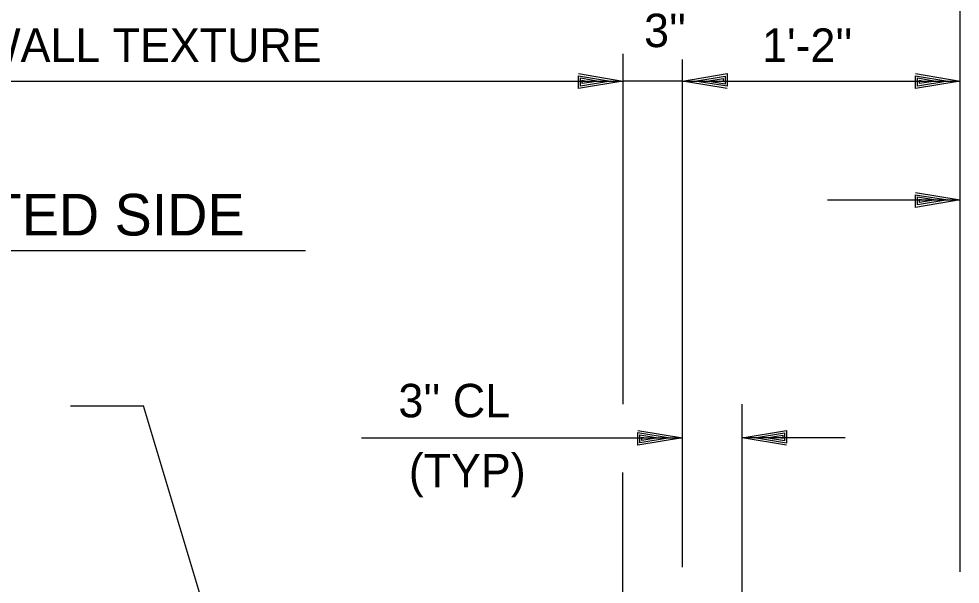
# Model space of a CAD drawing. Extents: x 22369.6 to 22428.3, y 22369.6 to 22415.
# Drawn here: x 22412.13 to 22417.4, y 22393.85 to 22397.02 of the extents above; entities that cross this region are included whole.
import ezdxf

# ---------------------------------------------------------------- set-up
doc = ezdxf.new("R2010")
doc.units = 0
for name, color, linetype in [('Level 1', 7, 'Continuous'), ('Level 10', 7, 'Continuous'), ('Level 2', 7, 'Continuous'), ('Level 4', 7, 'Continuous'), ('Level 8', 7, 'Continuous')]:
    doc.layers.add(name, color=color, linetype=linetype)

msp = doc.modelspace()

# ---------------------------------------------------------------- linework, layer by layer
at = {"layer": 'Level 1'}
for p, q in [((22417.4003, 22393.9179), (22417.4003, 22397.5025)), ((22415.5114, 22396.8216), (22415.5114, 22394.857)), ((22415.8447, 22393.9437), (22415.8447, 22396.7903)), ((22410.6541, 22396.6688), (22415.5114, 22396.6688)), ((22415.419, 22396.6688), (22415.419, 22396.6688)), ((22415.8447, 22396.6688), (22415.5114, 22396.6688)), ((22415.5114, 22396.6688), (22415.5114, 22396.6688)), ((22415.8447, 22396.6688), (22417.4003, 22396.6688)), ((22415.8447, 22396.6688), (22415.8447, 22396.6688)), ((22415.8447, 22396.6688), (22415.8447, 22396.6688)), ((22415.9372, 22396.6688), (22415.9372, 22396.6688)), ((22417.3078, 22396.6688), (22417.3078, 22396.6688)), ((22417.4003, 22396.6688), (22417.4003, 22396.6688)), ((22416.6564, 22396.0021), (22417.4003, 22396.0021)), ((22417.3078, 22396.0021), (22417.3078, 22396.0021)), ((22417.4003, 22396.0021), (22417.4003, 22396.0021)), ((22412.4169, 22394.8484), (22412.8251, 22394.8484)), ((22413.8278, 22391.5022), (22412.8251, 22394.8484)), ((22416.1781, 22392.5884), (22416.1781, 22394.857)), ((22414.0464, 22394.6688), (22415.8447, 22394.6688)), ((22415.7523, 22394.6688), (22415.7523, 22394.6688)), ((22415.8447, 22394.6688), (22415.8447, 22394.6688)), ((22416.7559, 22394.6688), (22416.1781, 22394.6688)), ((22416.1781, 22394.6688), (22416.1781, 22394.6688)), ((22416.2705, 22394.6688), (22416.2705, 22394.6688)), ((22415.5114, 22392.0875), (22415.5114, 22394.474))]:
    msp.add_line(p, q, dxfattribs=at)
at = {"layer": 'Level 10'}
msp.add_line((22410.5056, 22395.7182), (22413.7333, 22395.7182), dxfattribs=at)
at = {"layer": 'Level 2'}
for points in [[(22415.2621, 22396.7101), (22415.5114, 22396.6688), (22415.2621, 22396.6274), (22415.2621, 22396.6981), (22415.4421, 22396.6688), (22415.2728, 22396.6408), (22415.2728, 22396.6861), (22415.3754, 22396.6688), (22415.2834, 22396.6541), (22415.2834, 22396.6728), (22415.3061, 22396.6688)], [(22416.0941, 22396.6274), (22415.8447, 22396.6688), (22416.0941, 22396.7101), (22416.0941, 22396.6394), (22415.9141, 22396.6688), (22416.0834, 22396.6968), (22416.0834, 22396.6514), (22415.9807, 22396.6688), (22416.0727, 22396.6834), (22416.0727, 22396.6648), (22416.0501, 22396.6688)], [(22417.1509, 22396.7101), (22417.4003, 22396.6688), (22417.1509, 22396.6274), (22417.1509, 22396.6981), (22417.3309, 22396.6688), (22417.1616, 22396.6408), (22417.1616, 22396.6861), (22417.2643, 22396.6688), (22417.1723, 22396.6541), (22417.1723, 22396.6728), (22417.1949, 22396.6688)], [(22417.1509, 22396.0435), (22417.4003, 22396.0021), (22417.1509, 22395.9608), (22417.1509, 22396.0315), (22417.3309, 22396.0021), (22417.1616, 22395.9741), (22417.1616, 22396.0195), (22417.2643, 22396.0021), (22417.1723, 22395.9875), (22417.1723, 22396.0061), (22417.1949, 22396.0021)], [(22415.5954, 22394.7102), (22415.8447, 22394.6688), (22415.5954, 22394.6275), (22415.5954, 22394.6982), (22415.7754, 22394.6688), (22415.6061, 22394.6408), (22415.6061, 22394.6862), (22415.7088, 22394.6688), (22415.6168, 22394.6542), (22415.6168, 22394.6728), (22415.6394, 22394.6688)], [(22416.4274, 22394.6275), (22416.1781, 22394.6688), (22416.4274, 22394.7102), (22416.4274, 22394.6395), (22416.2474, 22394.6688), (22416.4167, 22394.6968), (22416.4167, 22394.6515), (22416.3141, 22394.6688), (22416.4061, 22394.6835), (22416.4061, 22394.6648), (22416.3834, 22394.6688)]]:
    msp.add_lwpolyline(points, dxfattribs=at)
at = {"layer": 'Level 8'}
for p, q in [((22415.4421, 22396.6688), (22415.4421, 22396.6688)), ((22415.5114, 22396.6688), (22415.5114, 22396.6688)), ((22415.8447, 22396.6688), (22415.8447, 22396.6688)), ((22415.9141, 22396.6688), (22415.9141, 22396.6688)), ((22417.3309, 22396.6688), (22417.3309, 22396.6688)), ((22417.4003, 22396.6688), (22417.4003, 22396.6688)), ((22417.3309, 22396.0021), (22417.3309, 22396.0021)), ((22417.4003, 22396.0021), (22417.4003, 22396.0021)), ((22415.7754, 22394.6688), (22415.7754, 22394.6688)), ((22415.8447, 22394.6688), (22415.8447, 22394.6688)), ((22416.1781, 22394.6688), (22416.1781, 22394.6688)), ((22416.2474, 22394.6688), (22416.2474, 22394.6688))]:
    msp.add_line(p, q, dxfattribs=at)

# ---------------------------------------------------------------- texts
at = {"layer": 'Level 10'}
msp.add_text('PROTECTED SIDE', height=0.233328, dxfattribs=at).set_placement((22410.6526, 22395.8031))
at = {"layer": 'Level 4'}
for s, height, p in [("3''", 0.1875, (22415.6297, 22396.8588)), ('WALL TEXTURE', 0.187495, (22411.9003, 22396.776)), ("1'-2''", 0.1875, (22416.2908, 22396.7761)), ("3'' CL", 0.1875, (22414.2534, 22394.7841)), ('(TYP)', 0.1875, (22414.3118, 22394.3918))]:
    msp.add_text(s, height=height, dxfattribs=at).set_placement(p)

doc.saveas('drawing.dxf')
